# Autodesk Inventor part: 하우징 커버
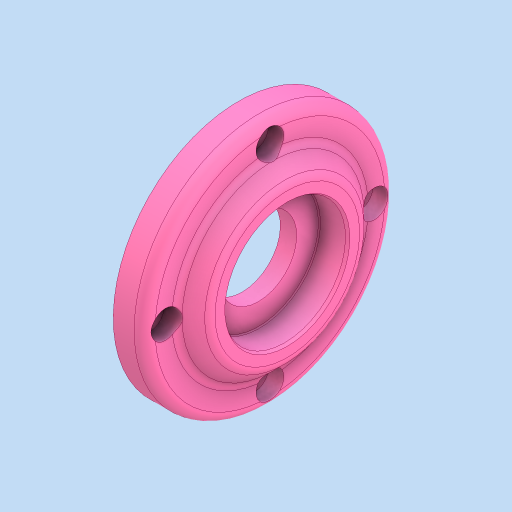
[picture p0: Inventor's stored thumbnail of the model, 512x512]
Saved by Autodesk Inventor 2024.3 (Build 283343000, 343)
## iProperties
Created: 2026-01
Part Number: 하우징 커버
Material: 알루미늄 6061
Document SubType Name: Modeling
Designer: PC2-02
Density: 2.7 g/cm^3
Appearance: 기본값
Author: jhkim
Sending System: Autodesk Inventor 2026
Preprocessor: ST-DEVELOPER v20.1
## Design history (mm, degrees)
node "하우징 커버1"
node "솔리드2"
node "솔리드1"
